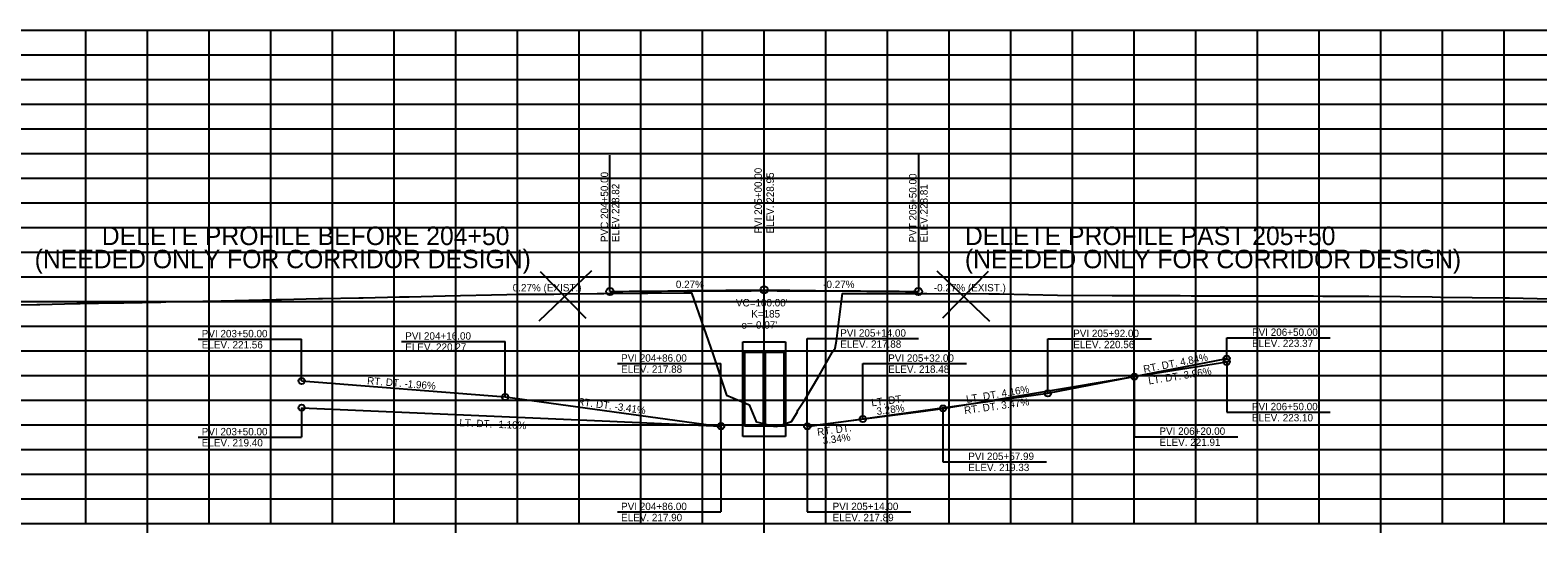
# Model space of a CAD drawing. Extents: x 1801553 to 1803097, y 521610 to 523048.
# Drawn here: x 1802036.6 to 1802525.6, y 522338.5 to 522501.5 of the extents above; entities that cross this region are included whole.
import ezdxf

# ---------------------------------------------------------------- set-up
doc = ezdxf.new("R2010")
doc.units = 0
for name, color, linetype in [('R_Axis', 7, 'Continuous'), ('R_Concrete', 7, 'Continuous'), ('R_Exist Surface', 7, 'Continuous'), ('R_Grid', 7, 'Continuous'), ('R_No Plot', 7, 'Continuous'), ('R_Vert Alg', 7, 'Continuous'), ('R_Vert Alg Annot', 7, 'Continuous')]:
    doc.layers.add(name, color=color, linetype=linetype)

msp = doc.modelspace()

# ---------------------------------------------------------------- linework, layer by layer
at = {"layer": 'R_Axis'}
msp.add_line((1801774.68, 522341.48), (1802774.68, 522341.48), dxfattribs=at)
at = {"layer": 'R_Concrete'}
for p, q in [((1802267.81, 522400.41), (1802281.55, 522400.41)), ((1802267.81, 522369.74), (1802267.81, 522400.41)), ((1802281.55, 522400.41), (1802281.55, 522369.74)), ((1802268.35, 522397.08), (1802268.35, 522373.08)), ((1802268.35, 522397.08), (1802281.01, 522397.08)), ((1802268.35, 522373.08), (1802268.35, 522397.08)), ((1802274.35, 522397.08), (1802274.35, 522373.08)), ((1802275.02, 522397.08), (1802275.02, 522373.08)), ((1802281.01, 522397.08), (1802281.01, 522373.08)), ((1802281.55, 522373.08), (1802268.35, 522373.08)), ((1802281.55, 522369.74), (1802267.81, 522369.74))]:
    msp.add_line(p, q, dxfattribs=at)
at = {"layer": 'R_Exist Surface'}
msp.add_lwpolyline([(1802026.71, 522412.32), (1802038.77, 522412.55), (1802039.78, 522412.57), (1802051.81, 522412.8), (1802052.84, 522412.82), (1802064.84, 522413.04), (1802065.9, 522413.07), (1802066.97, 522413.09), (1802078.97, 522413.32), (1802080.66, 522413.35), (1802098.53, 522413.73), (1802116.39, 522414.11), (1802118.1, 522414.14), (1802130.1, 522414.41), (1802131.39, 522414.43), (1802143.23, 522414.69), (1802144.68, 522414.72), (1802156.37, 522414.98), (1802157.97, 522415.01), (1802159.59, 522415.04), (1802171.25, 522415.3), (1802191.24, 522415.73), (1802194.31, 522415.82), (1802206.52, 522415.92), (1802208.52, 522415.94), (1802220.57, 522416.04), (1802222.73, 522416.06), (1802234.62, 522416.16), (1802236.95, 522416.18), (1802248.67, 522416.28), (1802251.16, 522416.3), (1802258.17, 522396.22), (1802262.44, 522383.09), (1802268.58, 522380.55), (1802269.81, 522380), (1802272.01, 522374.75), (1802272.23, 522374.46), (1802277.68, 522373.07), (1802278.55, 522372.92), (1802279.41, 522373.14), (1802283.57, 522374.54), (1802285.34, 522377.47), (1802285.55, 522378.21), (1802287.93, 522381.8), (1802292.45, 522389.26), (1802296.87, 522397.19), (1802297.76, 522398.38), (1802298.18, 522400.76), (1802299.13, 522408.55), (1802300.08, 522416.1), (1802303.92, 522416.1), (1802323.8, 522416.06), (1802327.44, 522416.05), (1802347.53, 522416.01), (1802350.99, 522415.95), (1802369.84, 522415.53), (1802387.55, 522415.46), (1802391.57, 522415.45), (1802409.64, 522415.39), (1802413.16, 522415.38), (1802425.23, 522415.35), (1802428.49, 522415.33), (1802440.59, 522415.3), (1802452.86, 522415.28), (1802455.82, 522415.26), (1802468.11, 522415.24), (1802470.73, 522415.21), (1802491.31, 522414.96), (1802494, 522414.94), (1802514.51, 522414.69), (1802516.38, 522414.65), (1802529.8, 522414.37)], dxfattribs=at)
at = {"layer": 'R_Grid'}
for p, q in [((1801774.68, 522501.48), (1802774.68, 522501.48)), ((1801774.68, 522501.48), (1802774.68, 522501.48)), ((1802054.68, 522341.48), (1802054.68, 522501.48)), ((1802074.68, 522341.48), (1802074.68, 522501.48)), ((1802094.68, 522341.48), (1802094.68, 522501.48)), ((1802114.68, 522341.48), (1802114.68, 522501.48)), ((1802134.68, 522341.48), (1802134.68, 522501.48)), ((1802154.68, 522341.48), (1802154.68, 522501.48)), ((1802174.68, 522341.48), (1802174.68, 522501.48)), ((1802194.68, 522341.48), (1802194.68, 522501.48)), ((1802214.68, 522341.48), (1802214.68, 522501.48)), ((1802234.68, 522341.48), (1802234.68, 522501.48)), ((1802254.68, 522341.48), (1802254.68, 522501.48)), ((1802274.68, 522341.48), (1802274.68, 522501.48)), ((1802294.68, 522341.48), (1802294.68, 522501.48)), ((1802314.68, 522341.48), (1802314.68, 522501.48)), ((1802334.68, 522341.48), (1802334.68, 522501.48)), ((1802354.68, 522341.48), (1802354.68, 522501.48)), ((1802374.68, 522341.48), (1802374.68, 522501.48)), ((1802394.68, 522341.48), (1802394.68, 522501.48)), ((1802414.68, 522341.48), (1802414.68, 522501.48)), ((1802434.68, 522341.48), (1802434.68, 522501.48)), ((1802454.68, 522341.48), (1802454.68, 522501.48)), ((1802474.68, 522341.48), (1802474.68, 522501.48)), ((1802494.68, 522341.48), (1802494.68, 522501.48)), ((1802514.68, 522341.48), (1802514.68, 522501.48)), ((1801774.68, 522493.48), (1802774.68, 522493.48)), ((1801774.68, 522485.48), (1802774.68, 522485.48)), ((1801774.68, 522477.48), (1802774.68, 522477.48)), ((1801774.68, 522469.48), (1802774.68, 522469.48)), ((1801774.68, 522461.48), (1802774.68, 522461.48)), ((1801774.68, 522453.48), (1802774.68, 522453.48)), ((1801774.68, 522445.48), (1802774.68, 522445.48)), ((1801774.68, 522437.48), (1802774.68, 522437.48)), ((1801774.68, 522429.48), (1802774.68, 522429.48)), ((1801774.68, 522421.48), (1802774.68, 522421.48)), ((1801774.68, 522413.48), (1802774.68, 522413.48)), ((1801774.68, 522405.48), (1802774.68, 522405.48)), ((1801774.68, 522397.48), (1802774.68, 522397.48)), ((1801774.68, 522389.48), (1802774.68, 522389.48)), ((1801774.68, 522381.48), (1802774.68, 522381.48)), ((1801774.68, 522373.48), (1802774.68, 522373.48)), ((1801774.68, 522365.48), (1802774.68, 522365.48)), ((1801774.68, 522357.48), (1802774.68, 522357.48)), ((1801774.68, 522349.48), (1802774.68, 522349.48)), ((1802074.68, 522338.48), (1802074.68, 522341.48)), ((1802174.68, 522338.48), (1802174.68, 522341.48)), ((1802274.68, 522338.48), (1802274.68, 522341.48)), ((1802474.68, 522338.48), (1802474.68, 522341.48))]:
    msp.add_line(p, q, dxfattribs=at)
at = {"layer": 'R_No Plot'}
for p, q in [((1802218.66, 522423.43), (1802201.57, 522407.09)), ((1802202, 522423.17), (1802216.87, 522408.12)), ((1802330.7, 522423.43), (1802347.79, 522407.09)), ((1802347.37, 522423.17), (1802332.49, 522408.12))]:
    msp.add_line(p, q, dxfattribs=at)
at = {"layer": 'R_Vert Alg'}
for p, q in [((1802249.68, 522417.01), (1802274.68, 522417.28)), ((1802274.68, 522417.28), (1802299.68, 522417)), ((1802366.68, 522383.72), (1802424.68, 522394.96)), ((1802394.68, 522389.12), (1802424.68, 522393.88)), ((1802124.68, 522387.72), (1802190.68, 522382.54)), ((1802332.67, 522378.8), (1802394.68, 522389.12)), ((1802190.68, 522382.54), (1802260.68, 522372.99)), ((1802306.68, 522375.4), (1802366.68, 522383.72)), ((1802124.68, 522379.06), (1802224.68, 522374.67)), ((1802288.68, 522373.04), (1802324.68, 522377.76)), ((1802288.68, 522372.99), (1802306.68, 522375.4)), ((1802324.68, 522377.76), (1802332.67, 522378.8)), ((1802224.68, 522374.67), (1802260.68, 522373.09))]:
    msp.add_line(p, q, dxfattribs=at)
msp.add_lwpolyline([(1802224.68, 522416.74), (1802226.76, 522416.76), (1802228.85, 522416.78), (1802230.93, 522416.8), (1802233.01, 522416.82), (1802235.1, 522416.84), (1802237.18, 522416.86), (1802239.26, 522416.87), (1802241.35, 522416.89), (1802243.43, 522416.9), (1802245.51, 522416.92), (1802247.6, 522416.93), (1802249.68, 522416.94), (1802251.76, 522416.95), (1802253.85, 522416.96), (1802255.93, 522416.97), (1802258.01, 522416.98), (1802260.1, 522416.98), (1802262.18, 522416.99), (1802264.26, 522417), (1802266.35, 522417), (1802268.43, 522417), (1802270.51, 522417), (1802272.6, 522417.01), (1802276.76, 522417.01), (1802278.85, 522417), (1802280.93, 522417), (1802283.01, 522417), (1802285.1, 522416.99), (1802287.18, 522416.99), (1802289.26, 522416.98), (1802291.35, 522416.97), (1802293.43, 522416.97), (1802295.51, 522416.96), (1802297.6, 522416.95), (1802299.68, 522416.94), (1802301.76, 522416.92), (1802303.85, 522416.91), (1802305.93, 522416.9), (1802308.01, 522416.88), (1802310.1, 522416.87), (1802312.18, 522416.85), (1802314.26, 522416.83), (1802316.35, 522416.81), (1802318.43, 522416.79), (1802320.51, 522416.77), (1802322.6, 522416.75), (1802324.68, 522416.73)], dxfattribs=at)
at = {"layer": 'R_Vert Alg Annot'}
for p, q in [((1802224.68, 522416.74), (1802224.68, 522460.94)), ((1802274.68, 522417.28), (1802274.68, 522461.48)), ((1802324.68, 522461.48), (1802324.68, 522416.73)), ((1802091.08, 522401.28), (1802124.68, 522401.28)), ((1802124.68, 522387.72), (1802124.68, 522401.28)), ((1802157.08, 522400.52), (1802190.68, 522400.52)), ((1802190.68, 522382.54), (1802190.68, 522400.52)), ((1802288.68, 522372.99), (1802288.68, 522401.49)), ((1802288.68, 522401.49), (1802324.71, 522401.49)), ((1802366.68, 522383.72), (1802366.68, 522401.35)), ((1802366.68, 522401.35), (1802400.28, 522401.35)), ((1802424.68, 522394.96), (1802424.68, 522401.74)), ((1802424.68, 522401.74), (1802458.28, 522401.74)), ((1802227.08, 522393.37), (1802260.68, 522393.37)), ((1802260.68, 522372.99), (1802260.68, 522393.37)), ((1802306.68, 522375.4), (1802306.68, 522393.34)), ((1802306.68, 522393.34), (1802340.28, 522393.34)), ((1802424.68, 522393.88), (1802424.68, 522377.62)), ((1802394.68, 522389.12), (1802394.68, 522369.65)), ((1802124.68, 522379.06), (1802124.68, 522369.5)), ((1802332.67, 522378.8), (1802332.67, 522361.5)), ((1802424.68, 522377.62), (1802458.28, 522377.62)), ((1802260.68, 522373.09), (1802260.68, 522345.25)), ((1802288.68, 522373.04), (1802288.68, 522345.25)), ((1802091.08, 522369.5), (1802124.68, 522369.5)), ((1802394.68, 522369.65), (1802428.28, 522369.65)), ((1802332.67, 522361.5), (1802366.27, 522361.5)), ((1802227.08, 522345.25), (1802260.68, 522345.25)), ((1802288.68, 522345.25), (1802322.28, 522345.25))]:
    msp.add_line(p, q, dxfattribs=at)
for centre, radius in [((1802224.68, 522416.74), 1.2), ((1802274.68, 522417.28), 1.2), ((1802324.68, 522416.73), 1.2), ((1802424.68, 522394.96), 1), ((1802424.68, 522393.88), 1), ((1802394.68, 522389.12), 1), ((1802124.68, 522387.72), 1), ((1802190.68, 522382.54), 1), ((1802366.68, 522383.72), 1), ((1802124.68, 522379.06), 1), ((1802306.68, 522375.4), 1), ((1802332.67, 522378.8), 1), ((1802260.68, 522373.09), 1), ((1802260.68, 522372.99), 1), ((1802288.68, 522373.04), 1), ((1802288.68, 522372.99), 1)]:
    msp.add_circle(centre, radius, dxfattribs=at)

# ---------------------------------------------------------------- texts
at = {"layer": 'R_No Plot'}
for s, p in [('DELETE PROFILE BEFORE 204+50', (1802059.87, 522431.79)), ('DELETE PROFILE PAST 205+50', (1802339.78, 522431.79)), ('(NEEDED ONLY FOR CORRIDOR DESIGN)', (1802038.09, 522424.27)), ('(NEEDED ONLY FOR CORRIDOR DESIGN)', (1802339.78, 522424.27))]:
    msp.add_text(s, height=6, dxfattribs=at).set_placement(p)
at = {"layer": 'R_Vert Alg Annot'}
for s, rotation, p in [('PVC 204+50.00', 90, (1802224.08, 522432.77)), ('PVI 205+00.00', 90, (1802273.93, 522435.53)), ('ELEV. 228.95', 90, (1802277.83, 522435.53)), ('PVT 205+50.00', 90, (1802324.08, 522432.62)), ('ELEV.228.82', 90, (1802227.68, 522432.77)), ('ELEV.228.81', 90, (1802327.68, 522432.62)), ('RT. DT. 4.84%', 10.9676, (1802397.9, 522390.33)), ('LT. DT. 3.96%', 9.0081, (1802399.46, 522386.58)), ('RT. DT. -1.96%', 355.5084, (1802145.85, 522386.66)), ('LT. DT. 4.16%', 9.4449, (1802340.4, 522380.58)), ('RT. DT. -3.41%', 352.2341, (1802214.01, 522379.96)), ('LT. DT.', 7.4655, (1802309.59, 522379.48)), ('RT. DT. 3.47%', 7.8936, (1802339.71, 522376.95)), ('LT. DT. -1.10%', 357.4897, (1802175.78, 522373.03)), ('3.28%', 7.4655, (1802311.28, 522376.67)), ('RT. DT.', 7.6126, (1802292.02, 522369.96)), ('3.34%', 7.6126, (1802293.78, 522367.17))]:
    msp.add_text(s, height=2.4, rotation=rotation, dxfattribs=at).set_placement(p)
for s, p in [('0.27%', (1802246.04, 522417.86)), ('-0.27%', (1802293.82, 522417.86)), ('0.27% (EXIST.)', (1802193.14, 522416.77)), ('-0.27% (EXIST.)', (1802329.7, 522416.77)), ("VC=100.00'", (1802265.53, 522411.89)), ('K=185', (1802270.47, 522408.29)), ("e=-0.07'", (1802267.31, 522404.69)), ('PVI 206+50.00', (1802432.9, 522402.34)), ('PVI 203+50.00', (1802092.28, 522401.88)), ('ELEV. 221.56', (1802092.28, 522398.28)), ('PVI 204+16.00', (1802158.28, 522401.12)), ('ELEV. 220.27', (1802158.28, 522397.52)), ('PVI 205+14.00', (1802299.34, 522402.09)), ('ELEV. 217.88', (1802299.34, 522398.49)), ('PVI 205+92.00', (1802374.9, 522401.95)), ('ELEV. 220.56', (1802374.9, 522398.35)), ('ELEV. 223.37', (1802432.9, 522398.74)), ('PVI 204+86.00', (1802228.28, 522393.97)), ('PVI 205+32.00', (1802314.9, 522393.94)), ('ELEV. 217.88', (1802228.28, 522390.37)), ('ELEV. 218.48', (1802314.9, 522390.34)), ('PVI 206+50.00', (1802432.87, 522378.22)), ('ELEV. 223.10', (1802432.87, 522374.62)), ('PVI 203+50.00', (1802092.28, 522370.1)), ('PVI 206+20.00', (1802402.87, 522370.25)), ('ELEV. 219.40', (1802092.28, 522366.5)), ('ELEV. 221.91', (1802402.87, 522366.65)), ('PVI 205+57.99', (1802340.87, 522362.1)), ('ELEV. 219.33', (1802340.87, 522358.5)), ('PVI 204+86.00', (1802228.28, 522345.85)), ('PVI 205+14.00', (1802296.87, 522345.85)), ('ELEV. 217.90', (1802228.28, 522342.25)), ('ELEV. 217.89', (1802296.87, 522342.25))]:
    msp.add_text(s, height=2.4, dxfattribs=at).set_placement(p)

doc.saveas('drawing.dxf')
